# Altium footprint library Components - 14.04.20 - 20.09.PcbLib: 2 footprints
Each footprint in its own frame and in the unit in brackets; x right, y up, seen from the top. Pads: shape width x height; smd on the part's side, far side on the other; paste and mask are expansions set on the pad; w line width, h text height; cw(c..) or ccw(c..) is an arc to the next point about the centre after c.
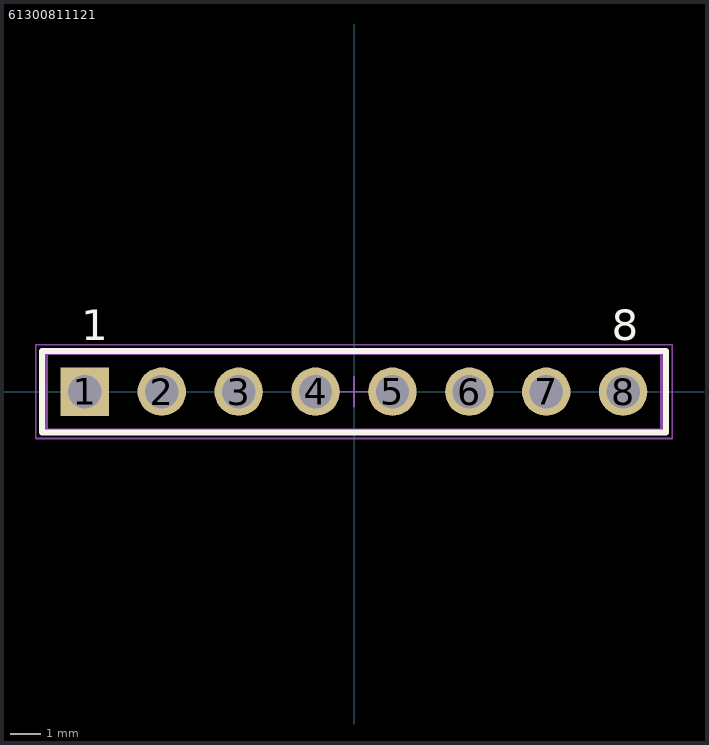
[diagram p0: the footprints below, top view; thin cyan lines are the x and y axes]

## 61300811121 [mm] "Pin Header, pitch 2.54 mm, THT, Vertical, single row, 8p"
height 8.54
pads (8):
  rect 1.6x1.6 hole 1.1: 1(-8.89,0)
  round 1.6 hole 1.1: 2(-6.35,0) 3(-3.81,0) 4(-1.27,0) 5(1.27,0) 6(3.81,0) 7(6.35,0) 8(8.89,0)
Top Overlay:
  lines w0.2: -10.31,-1.345 10.31,-1.345 10.31,1.345 -10.31,1.345 -10.31,-1.345
  text "1" at -9.01,1.7 h1.02
  text "8" at 8.51,1.7 h1.02
Mechanical 13:
  lines w0.1: -10.16,-1.27 -10.16,1.27 10.16,1.27 10.16,-1.27 -10.16,-1.27
Mechanical 15:
  lines w0.05: -0.5,0 0.5,0 ; 0,-0.5 0,0.5 ; -10.51,-1.545 -10.51,1.545 10.51,1.545 10.51,-1.545 -10.51,-1.545
3D body "61300811121.stp": height 8.57, standoff -2.97, extent -10.16,-1.27 10.16,1.27

## PCBComponent_1 [mm]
